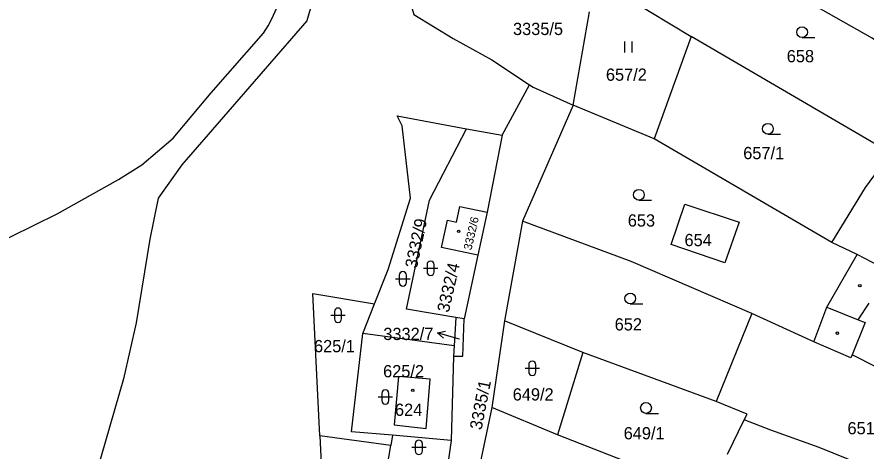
# Model space of a CAD drawing. Extents: x -600849 to -599899, y -1204328 to -1203436.
# Drawn here: x -600587.3 to -600469.3, y -1203570.8 to -1203510.5 of the extents above; entities that cross this region are included whole.
import ezdxf

# ---------------------------------------------------------------- set-up
doc = ezdxf.new("R2010")
doc.units = 0
for name, color, linetype in [('Vrstva 1', 7, 'Continuous'), ('Vrstva 2', 7, 'Continuous'), ('Vrstva 3', 7, 'Continuous'), ('Vrstva 4', 7, 'Continuous'), ('Vrstva 5', 7, 'Continuous'), ('Vrstva 7', 7, 'Continuous')]:
    doc.layers.add(name, color=color, linetype=linetype)

msp = doc.modelspace()

# ---------------------------------------------------------------- linework, layer by layer
at = {"layer": 'Vrstva 1'}
for p, q in [((-600502.41, -1203507.91), (-600493.64, -1203513.21)), ((-600510.04, -1203522.74), (-600507.79, -1203509.79)), ((-600493.64, -1203513.21), (-600498.77, -1203527.42)), ((-600465.92, -1203529.41), (-600493.64, -1203513.21)), ((-600519.89, -1203526.91), (-600516.1, -1203519.91)), ((-600516.1, -1203519.91), (-600515.6, -1203520.24)), ((-600515.6, -1203520.24), (-600510.04, -1203522.74)), ((-600510.04, -1203522.74), (-600517.08, -1203538.84)), ((-600498.77, -1203527.42), (-600510.04, -1203522.74)), ((-600524.84, -1203526.02), (-600519.89, -1203526.91)), ((-600519.89, -1203526.91), (-600521.99, -1203537.61)), ((-600474.09, -1203541.81), (-600498.77, -1203527.42)), ((-600521.99, -1203537.61), (-600523.27, -1203543.59)), ((-600517.08, -1203538.84), (-600519.57, -1203552.72)), ((-600470.59, -1203543.47), (-600474.09, -1203541.81)), ((-600523.27, -1203543.59), (-600525.2, -1203552.43)), ((-600539.28, -1203554.47), (-600537.63, -1203550.34)), ((-600526.33, -1203552.24), (-600526.58, -1203556.16)), ((-600525.2, -1203552.43), (-600526.33, -1203552.24)), ((-600519.57, -1203552.72), (-600521.35, -1203564.72)), ((-600508.71, -1203557.08), (-600519.57, -1203552.72)), ((-600485.23, -1203551.7), (-600490.17, -1203563.9)), ((-600476.58, -1203555.6), (-600485.23, -1203551.7)), ((-600526.58, -1203556.16), (-600539.28, -1203554.47)), ((-600526.58, -1203556.16), (-600526.67, -1203557.62)), ((-600471.46, -1203557.85), (-600476.58, -1203555.6)), ((-600508.71, -1203557.08), (-600512.22, -1203568.54)), ((-600490.17, -1203563.9), (-600508.71, -1203557.08)), ((-600526.67, -1203557.62), (-600526.97, -1203569.31)), ((-600521.35, -1203564.72), (-600523.82, -1203576.55)), ((-600512.22, -1203568.54), (-600521.35, -1203564.72)), ((-600488.58, -1203571.21), (-600486.26, -1203566.43)), ((-600535.37, -1203570.01), (-600545.25, -1203568.67)), ((-600535.14, -1203568.6), (-600535.37, -1203570.01)), ((-600526.97, -1203569.31), (-600535.14, -1203568.6)), ((-600526.97, -1203569.31), (-600527.85, -1203575.45)), ((-600536.07, -1203574.02), (-600535.37, -1203570.01))]:
    msp.add_line(p, q, dxfattribs=at)
for points in [[(-600645.19, -1203571.16), (-600643.45, -1203572.4), (-600642.87, -1203572.55), (-600642.3, -1203572.31), (-600640.94, -1203570.26), (-600640.09, -1203571.18), (-600633.19, -1203566.46), (-600625.08, -1203560.78), (-600591.46, -1203542.4), (-600591.38, -1203542.56), (-600581.75, -1203537.86), (-600573.23, -1203533.09), (-600569.96, -1203531.02), (-600565.64, -1203527.34), (-600560.36, -1203521.05), (-600553.06, -1203512.74), (-600552.4, -1203511.74), (-600551.87, -1203510.65), (-600546.9, -1203499.62), (-600543.15, -1203494.15), (-600536.39, -1203488.52), (-600530.27, -1203484.25)], [(-600450.34, -1203526.35), (-600468.48, -1203513.43), (-600496.38, -1203497.68)], [(-600542.5, -1203502.23), (-600546.27, -1203508.32), (-600547.05, -1203511.06), (-600564.41, -1203531.04), (-600567.71, -1203535.68)], [(-600532.93, -1203507.61), (-600532.18, -1203510.17), (-600526.7, -1203513.51), (-600521.35, -1203516.47), (-600516.1, -1203519.91)], [(-600537.63, -1203550.34), (-600535.73, -1203545.56), (-600532.64, -1203535.66), (-600533.78, -1203525.6), (-600534.49, -1203524.23), (-600524.84, -1203526.02)], [(-600526.33, -1203552.24), (-600533.22, -1203551.08), (-600529.98, -1203535.94), (-600524.84, -1203526.02)], [(-600474.09, -1203541.81), (-600469.44, -1203534.18), (-600465.92, -1203529.41)], [(-600567.71, -1203535.68), (-600568.88, -1203541.35), (-600570.78, -1203553), (-600572.53, -1203560.77), (-600577.53, -1203578.08), (-600582.45, -1203585.75), (-600582.83, -1203594.05), (-600582.58, -1203597.57), (-600584.26, -1203601.02), (-600586.62, -1203603.76), (-600592.16, -1203610.92), (-600599.38, -1203621.05), (-600601.73, -1203624.09), (-600605.79, -1203627.61)], [(-600523.27, -1203543.59), (-600528.34, -1203542.51), (-600527.52, -1203538.71), (-600526.25, -1203538.98), (-600525.78, -1203536.8), (-600521.99, -1203537.61)], [(-600488.98, -1203544.63), (-600496.43, -1203542.12), (-600494.52, -1203536.48)], [(-600494.52, -1203536.48), (-600486.95, -1203538.99), (-600488.98, -1203544.63)], [(-600485.23, -1203551.7), (-600502, -1203544.45), (-600517.08, -1203538.84)], [(-600476.58, -1203555.6), (-600474.81, -1203550.8), (-600470.59, -1203543.47)], [(-600466.38, -1203545.34), (-600466.53, -1203545.58), (-600468.43, -1203544.59), (-600470.59, -1203543.47)], [(-600545.25, -1203568.67), (-600546.23, -1203548.89), (-600537.63, -1203550.34)], [(-600526.67, -1203557.62), (-600525.35, -1203557.59), (-600525.2, -1203552.43)], [(-600535.14, -1203568.6), (-600540.82, -1203568.11), (-600539.28, -1203554.47)], [(-600461.29, -1203562.48), (-600471.29, -1203557.43), (-600471.46, -1203557.85)], [(-600534.89, -1203567.15), (-600530.48, -1203567.64), (-600529.91, -1203560.81), (-600534.31, -1203560.43), (-600534.89, -1203567.15)], [(-600486.26, -1203566.43), (-600485.88, -1203565.66), (-600490.17, -1203563.9)], [(-600459.28, -1203578.17), (-600460.53, -1203577.18), (-600467.84, -1203573.55), (-600475.84, -1203570.31), (-600482.56, -1203567.9), (-600486.26, -1203566.43)], [(-600545.25, -1203568.67), (-600544.59, -1203582.14), (-600537.72, -1203582.87)], [(-600491.12, -1203576.92), (-600498.27, -1203573.51), (-600502.86, -1203572.19), (-600512.22, -1203568.54)]]:
    msp.add_lwpolyline(points, dxfattribs=at)
at = {"layer": 'Vrstva 3'}
for p, q in [((-600478.23, -1203513.36), (-600476.48, -1203513.36)), ((-600502.86, -1203515.42), (-600502.86, -1203513.92)), ((-600501.86, -1203515.42), (-600501.86, -1203513.92)), ((-600482.98, -1203526.78), (-600481.23, -1203526.78)), ((-600500.91, -1203535.95), (-600499.16, -1203535.95)), ((-600530.85, -1203545.4), (-600528.85, -1203545.4)), ((-600530.35, -1203544.9), (-600530.35, -1203545.9)), ((-600529.35, -1203545.9), (-600529.35, -1203544.9)), ((-600534.71, -1203546.87), (-600532.71, -1203546.87)), ((-600534.21, -1203546.37), (-600534.21, -1203547.37)), ((-600533.21, -1203547.37), (-600533.21, -1203546.37)), ((-600502.11, -1203550.35), (-600500.36, -1203550.35)), ((-600543.22, -1203551.42), (-600543.22, -1203552.42)), ((-600542.22, -1203552.42), (-600542.22, -1203551.42)), ((-600543.72, -1203551.92), (-600541.72, -1203551.92)), ((-600516.72, -1203559.29), (-600514.72, -1203559.29)), ((-600516.22, -1203558.79), (-600516.22, -1203559.79)), ((-600515.22, -1203559.79), (-600515.22, -1203558.79)), ((-600537.14, -1203563.28), (-600535.14, -1203563.28)), ((-600536.64, -1203562.78), (-600536.64, -1203563.78)), ((-600535.64, -1203563.78), (-600535.64, -1203562.78)), ((-600499.92, -1203565.55), (-600498.17, -1203565.55)), ((-600532.48, -1203570.27), (-600530.48, -1203570.27)), ((-600531.98, -1203569.77), (-600531.98, -1203570.77)), ((-600530.98, -1203570.77), (-600530.98, -1203569.77))]:
    msp.add_line(p, q, dxfattribs=at)
for centre in [(-600478.23, -1203512.61), (-600482.98, -1203526.03), (-600500.91, -1203535.2), (-600502.11, -1203549.6), (-600499.92, -1203564.8)]:
    msp.add_circle(centre, 0.75, dxfattribs=at)
for centre, start, end in [((-600529.85, -1203544.9), 0, 180), ((-600533.71, -1203546.37), 0, 180), ((-600529.85, -1203545.9), 180, 359.9879), ((-600533.71, -1203547.37), 180, 359.9879), ((-600542.72, -1203551.42), 0, 180), ((-600542.72, -1203552.42), 180, 359.9879), ((-600515.72, -1203558.79), 0, 180), ((-600515.72, -1203559.79), 180, 359.9879), ((-600536.14, -1203562.78), 0, 180), ((-600536.14, -1203563.78), 180, 359.9879), ((-600531.48, -1203569.77), 0, 180), ((-600531.48, -1203570.77), 180, 359.9879)]:
    msp.add_arc(centre, 0.5, start, end, dxfattribs=at)
at = {"layer": 'Vrstva 4'}
for p, q in [((-600470.43, -1203552.55), (-600468.92, -1203550.24)), ((-600474.81, -1203550.8), (-600470.43, -1203552.55)), ((-600470.43, -1203552.55), (-600469.45, -1203552.94)), ((-600469.45, -1203552.94), (-600471.29, -1203557.43))]:
    msp.add_line(p, q, dxfattribs=at)
at = {"layer": 'Vrstva 5'}
for centre in [(-600525.95, -1203540.28), (-600470.21, -1203547.82), (-600473.33, -1203554.41), (-600532.33, -1203562.35)]:
    msp.add_circle(centre, 0.175, dxfattribs=at)
at = {"layer": 'Vrstva 7'}
for p, q in [((-600528.89, -1203554.35), (-600527.78, -1203554.15)), ((-600526, -1203555.18), (-600528.89, -1203554.35)), ((-600528.89, -1203554.35), (-600528.06, -1203555.11)), ((-600525.82, -1203555.23), (-600526, -1203555.18))]:
    msp.add_line(p, q, dxfattribs=at)

# ---------------------------------------------------------------- texts
at = {"layer": 'Vrstva 2'}
for s, p in [('3335/5', (-600518.4, -1203513.01)), ('658', (-600480.36, -1203516.79)), ('657/2', (-600505.49, -1203519.36)), ('657/1', (-600486.41, -1203530.25)), ('653', (-600502.45, -1203539.61)), ('654', (-600494.57, -1203542.33)), ('652', (-600504.27, -1203554.04)), ('3332/7', (-600536.42, -1203555.37)), ('625/1', (-600546.05, -1203557.06)), ('625/2', (-600536.45, -1203560.54)), ('649/2', (-600518.44, -1203563.77)), ('624', (-600534.8, -1203565.9)), ('651', (-600471.92, -1203568.46)), ('649/1', (-600503.02, -1203569.16))]:
    msp.add_text(s, height=1.7, dxfattribs=at).set_placement(p)
for s, height, rotation, p in [('3332/9', 1.7, 78, (-600531.77, -1203545.51)), ('3332/6', 1.14, 77, (-600524.18, -1203542.95)), ('3332/4', 1.7, 77, (-600527.33, -1203551.64)), ('3335/1', 1.7, 79, (-600522.77, -1203567.94))]:
    msp.add_text(s, height=height, rotation=rotation, dxfattribs=at).set_placement(p)

doc.saveas('drawing.dxf')
